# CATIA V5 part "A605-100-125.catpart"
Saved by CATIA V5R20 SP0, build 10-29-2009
Part number: A605-100-125
Source: Unknown
Property "A": "70.000"
Property "ARTICLENO": "A605-100-125"
Property "BOMINFO": "A605-100-125"
Property "CODE": "A605-100-125"
Property "D": "9.000"
Property "FORM": "C"
Property "L": "125.000"
Property "L1": "95.000"
Property "LINA": "A605-100-125"
Property "NB": "A605-100-125"
Property "NBSYN": "$CODE."
Property "NN": "A605"
Property "NT": "Wear Plates, self-lubricating"
Property "SCREW": "4*M8X16"
Property "SUPPLIER": "CF"
Property "W": "100.000"
Bounding box of the stored display mesh (mm): x -100 to 0, y 0 to 5, z -125 to 0
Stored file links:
  C:\Users\Utente\Desktop\3D files A605\A605-100-125.catpart
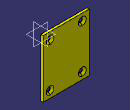
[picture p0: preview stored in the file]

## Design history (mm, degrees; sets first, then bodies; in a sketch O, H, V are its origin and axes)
Body1 "Geometry.1" (main body)
  Solid1 "A605-100-125.catpart": solid without history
